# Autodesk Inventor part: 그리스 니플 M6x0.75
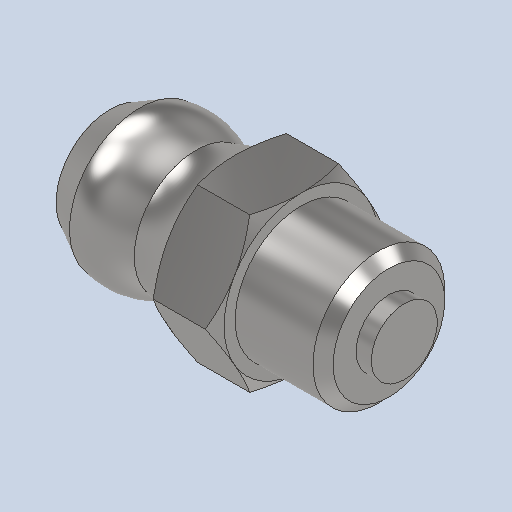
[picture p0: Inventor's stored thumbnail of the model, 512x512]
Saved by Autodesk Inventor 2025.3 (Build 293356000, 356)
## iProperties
Created: 2025-10
Part Number: 그리스 니플 M6x0.75
Material: 강철, 연강
Description: 윤활 니플, 원추 유형 A
Document SubType Name: Modeling
Designer: USER
Density: 7.85 g/cm^3
Appearance: 기본값
Author: jhkim
Sending System: Autodesk Inventor 2026
Preprocessor: ST-DEVELOPER v20.1
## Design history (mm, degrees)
feature "Solid1"
node "솔리드1"
